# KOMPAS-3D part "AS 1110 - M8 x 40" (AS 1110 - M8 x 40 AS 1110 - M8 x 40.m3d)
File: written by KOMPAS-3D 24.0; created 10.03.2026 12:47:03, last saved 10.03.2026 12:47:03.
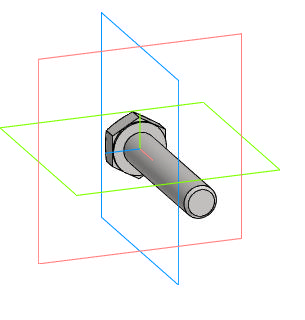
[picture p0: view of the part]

Document properties: Автор: R2D2; Полное имя файла: E:\Работа\Зайцев\BV3232P(4pc)-FP-3WL-F-ISO-H Кран шаровой DN.ru Ду15-100 Ру16\DN50\исходные материалы\AS 1110 - M8 x 40 AS 1110 - M8 x 40.m3d

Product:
- Body: Solid1  | qty 1
- Part/product: AS 1110 - M8 x 40
    Комментарий: Болты и винты   шестигранные точные   метрические ISO
    additional columns: Сталь, мягкая

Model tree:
1. Solid1  (labels: Solid1)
